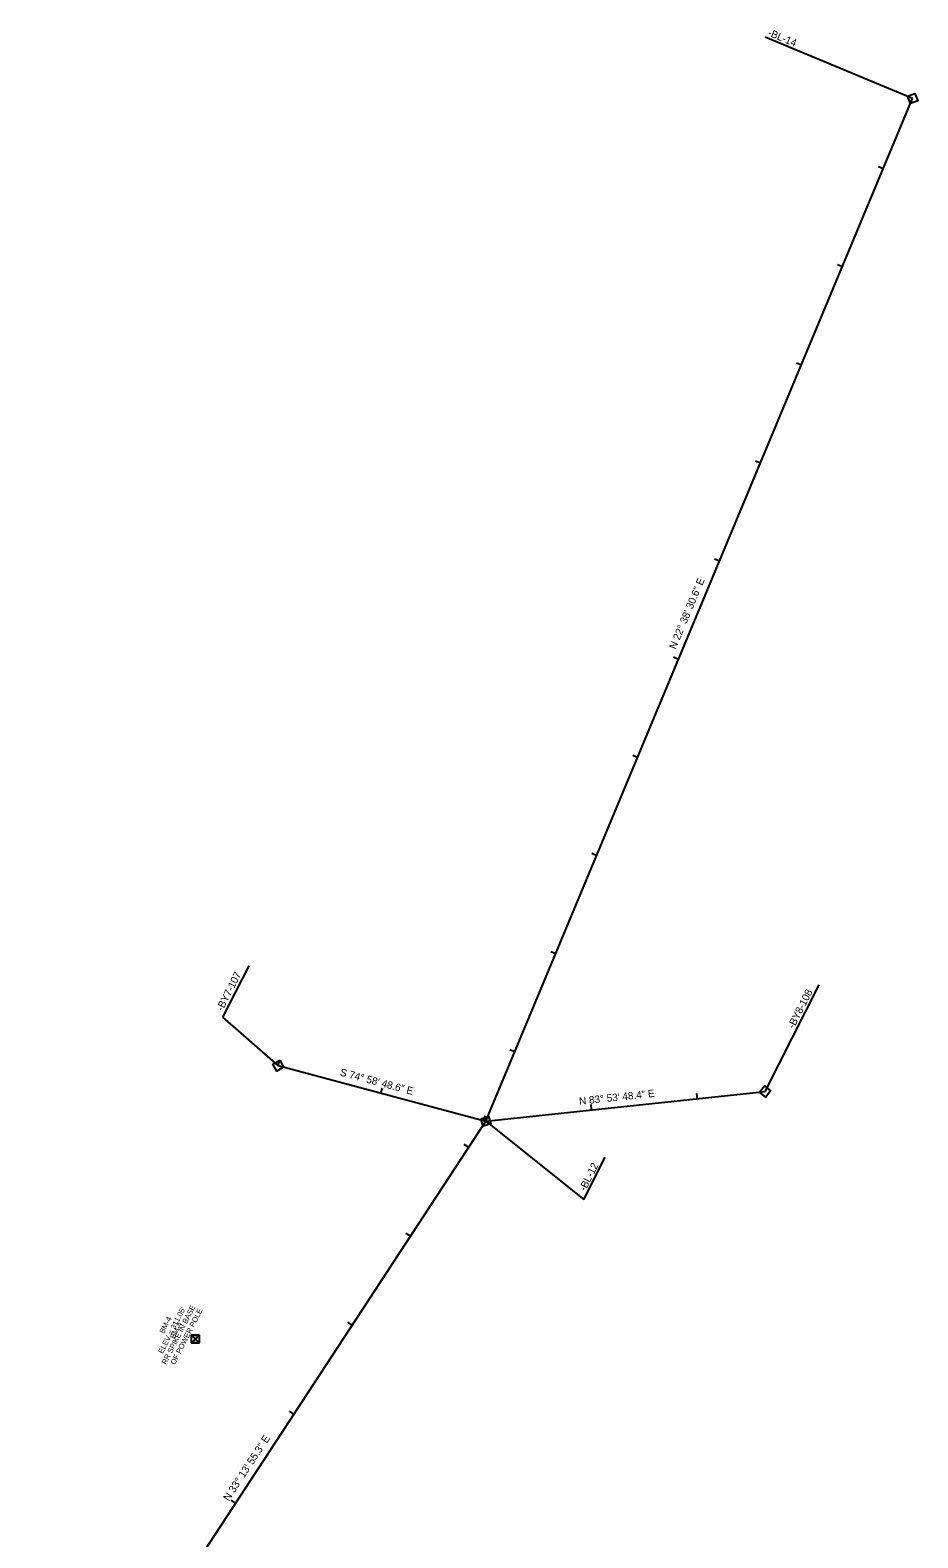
# Model space of a CAD drawing. Extents: x 1975258 to 1978652, y 778250 to 783549.
# Drawn here: x 1977700 to 1978534, y 782131 to 783549 of the extents above; entities that cross this region are included whole.
import ezdxf

# ---------------------------------------------------------------- set-up
doc = ezdxf.new("R2010")
doc.units = 0
for name, color, linetype in [('Prop Drainage Structure Drop Inlet Grate 2 Narrow Slots and Flat Grates 840 29 Label', 7, 'Continuous'), ('Prop Drainage Structure Drop Inlet Grate 2 Narrow Slots and Sag Grates 840 24 CELL', 7, 'Continuous'), ('Prop Erosion Rip Rap Pad at Outlet CELL', 7, 'Continuous'), ('Prop SS Fill Line', 7, 'Continuous'), ('Prop SS Transition Line', 7, 'Continuous'), ('Sheet Data Field CELL', 7, 'Continuous'), ('Sheet Sticker Preliminary CELL', 7, 'Continuous'), ('Sheet Typical CELL', 7, 'Continuous')]:
    doc.layers.add(name, color=color, linetype=linetype)

msp = doc.modelspace()

# ---------------------------------------------------------------- linework, layer by layer
at = {"layer": 'Prop Drainage Structure Drop Inlet Grate 2 Narrow Slots and Sag Grates 840 24 CELL'}
for p, q in [((1978529.3, 783484.7), (1978390.8, 783542.4)), ((1977880.9, 782620.6), (1977905.5, 782669.1)), ((1978390.6, 782550.8), (1978441.5, 782651.2)), ((1977932.9, 782575.1), (1977880.9, 782620.6)), ((1978128.1, 782522.8), (1978220.1, 782449.3)), ((1978220.1, 782449.3), (1978240.1, 782488.9))]:
    msp.add_line(p, q, dxfattribs=at)
at = {"layer": 'Prop SS Transition Line'}
for p, q in [((1978529.3, 783484.7), (1978529.3, 783484.7)), ((1977932.9, 782575.1), (1977932.9, 782575.1)), ((1978390.6, 782550.8), (1978390.6, 782550.8)), ((1978128.1, 782522.8), (1978128.1, 782522.8))]:
    msp.add_line(p, q, dxfattribs=at)
for points in [[(1978524.5, 783486.7), (1978531.3, 783489.5), (1978534.2, 783482.6), (1978527.3, 783479.8)], [(1977934.4, 782580.1), (1977938, 782573.7), (1977931.5, 782570), (1977927.9, 782576.5)], [(1978385.4, 782550.2), (1978390, 782556.1), (1978395.8, 782551.5), (1978391.3, 782545.6)], [(1978123.4, 782525.2), (1978130.5, 782527.4), (1978132.7, 782520.3), (1978125.7, 782518.1)]]:
    msp.add_lwpolyline(points, close=True, dxfattribs=at)
at = {"layer": 'Sheet Data Field CELL'}
for p, q in [((1978501.7, 783418.6), (1978497.1, 783420.5)), ((1978463.2, 783326.3), (1978458.6, 783328.2)), ((1978424.7, 783234), (1978420.1, 783235.9)), ((1978386.2, 783141.7), (1978381.6, 783143.6)), ((1978347.7, 783049.4), (1978343.1, 783051.4)), ((1978309.2, 782957.1), (1978304.6, 782959.1)), ((1978270.7, 782864.8), (1978266.1, 782866.8)), ((1978232.3, 782772.5), (1978227.6, 782774.5)), ((1978193.8, 782680.3), (1978189.1, 782682.2)), ((1977932.9, 782575.1), (1977934.2, 782580)), ((1978155.3, 782588), (1978150.6, 782589.9)), ((1978029.5, 782549.2), (1978030.8, 782554)), ((1978227.5, 782533.4), (1978227, 782538.4)), ((1978326.9, 782544), (1978326.4, 782549)), ((1978126.1, 782523.3), (1978127.4, 782528.1)), ((1978128.1, 782522.8), (1978127.5, 782527.7)), ((1978112, 782498.2), (1978107.8, 782500.9)), ((1978057.2, 782414.6), (1978053, 782417.3)), ((1978002.4, 782330.9), (1977998.2, 782333.7)), ((1977947.6, 782247.3), (1977943.4, 782250)), ((1977892.8, 782163.6), (1977888.6, 782166.4))]:
    msp.add_line(p, q, dxfattribs=at)
at = {"layer": 'Sheet Sticker Preliminary CELL'}
msp.add_line((1977855, 782318), (1977855, 782318), dxfattribs=at)
msp.add_lwpolyline([(1977851.4, 782321.6), (1977858.6, 782321.6), (1977858.6, 782314.4), (1977851.4, 782314.4)], close=True, dxfattribs=at)
for points in [[(1977858.6, 782321.6), (1977851.4, 782314.4), (1977855, 782318), (1977858.6, 782314.4), (1977851.4, 782321.6)], [(1977855, 782318), (1977858.6, 782321.6), (1977851.4, 782321.6), (1977855, 782318)], [(1977855, 782318), (1977851.4, 782314.4), (1977858.6, 782314.4), (1977855, 782318)]]:
    msp.add_lwpolyline(points, dxfattribs=at)
at = {"layer": 'Sheet Typical CELL'}
for p, q in [((1978128.1, 782522.8), (1978529.3, 783484.7)), ((1977932.9, 782575.1), (1978128.1, 782522.8)), ((1978128.1, 782522.8), (1978390.6, 782550.8)), ((1977699.7, 781869), (1978128.1, 782522.8))]:
    msp.add_line(p, q, dxfattribs=at)

# ---------------------------------------------------------------- texts
at = {"layer": 'Prop Drainage Structure Drop Inlet Grate 2 Narrow Slots and Flat Grates 840 29 Label'}
for s, rotation, p in [('N 22%%d 38\' 30.6" E', 67.3582, (1978306.5, 782966.1)), ('S 74%%d 58\' 48.6" E', 344.9802, (1977990.5, 782565.9)), ('N 83%%d 53\' 48.4" E', 6.1032, (1978216.1, 782538.2)), ('N 33%%d 13\' 55.3" E', 56.768, (1977886.5, 782165))]:
    msp.add_text(s, height=7, rotation=rotation, dxfattribs=at).set_placement(p)
at = {"layer": 'Prop Drainage Structure Drop Inlet Grate 2 Narrow Slots and Sag Grates 840 24 CELL'}
for s, rotation, p in [('-BL-14 ', 337.3582, (1978392.5, 783544)), ('-BY7-107', 63.1198, (1977880.5, 782625.8)), ('-BY8-108 ', 63.1198, (1978417.6, 782609.4)), ('-BL-12 ', 63.1198, (1978221.5, 782456.4))]:
    msp.add_text(s, height=7, rotation=rotation, dxfattribs=at).set_placement(p)
at = {"layer": 'Prop Erosion Rip Rap Pad at Outlet CELL'}
msp.add_text('BM-4', height=5, rotation=63.1198, dxfattribs=at).set_placement((1977835.5, 782317.6))
at = {"layer": 'Prop SS Fill Line'}
for s, p in [("ELEV = 311.05'", (1977824.3, 782303.8)), ('BM-4', (1977825.4, 782322.7)), ('RR SPIKE IN BASE', (1977827.5, 782293.5)), ('OF POWER POLE', (1977835.8, 782293.4))]:
    msp.add_text(s, height=5, rotation=63.1198, dxfattribs=at).set_placement(p)

doc.saveas('drawing.dxf')
